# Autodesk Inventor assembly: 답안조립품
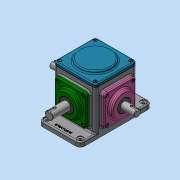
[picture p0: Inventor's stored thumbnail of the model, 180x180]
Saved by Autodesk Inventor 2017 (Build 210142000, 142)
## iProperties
Part Number: 답안조립품
Material: 일반
Document SubType Name: Assembly
Designer: MRC
Author: MRC
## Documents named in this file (16)
- C:\Users\MRC\OneDrive\바탕 화면\620307V1011\답안조립품.iam
- C:\Users\MRC\OneDrive\바탕 화면\620307V1011\본체.ipt
- C:\Users\MRC\OneDrive\바탕 화면\620307V1011\개스킷.ipt
- C:\Users\MRC\OneDrive\바탕 화면\620307V1011\메인베벨기어.ipt
- C:\Users\MRC\OneDrive\바탕 화면\620307V1011\메인축.ipt
- C:\Users\MRC\OneDrive\바탕 화면\620307V1011\메인커버.ipt
- C:\Users\MRC\OneDrive\바탕 화면\620307V1011\베어링 6203.ipt
- C:\Users\MRC\OneDrive\바탕 화면\620307V1011\베어링 6204.ipt
- C:\Users\MRC\OneDrive\바탕 화면\620307V1011\볼트 M4.ipt
- C:\Users\MRC\OneDrive\바탕 화면\620307V1011\상부커버.ipt
- C:\Users\MRC\OneDrive\바탕 화면\620307V1011\서브베벨기어.ipt
- C:\Users\MRC\OneDrive\바탕 화면\620307V1011\서브축.ipt
- C:\Users\MRC\OneDrive\바탕 화면\620307V1011\서브커버.ipt
- C:\Users\MRC\OneDrive\바탕 화면\620307V1011\오일 실 17 32 8.ipt
- C:\Users\MRC\OneDrive\바탕 화면\620307V1011\오일 실 20 35 8.ipt
- C:\Users\MRC\OneDrive\바탕 화면\620307V1011\키 4x4.ipt
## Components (1 placed, 1 different names)
1. 개스킷:1
